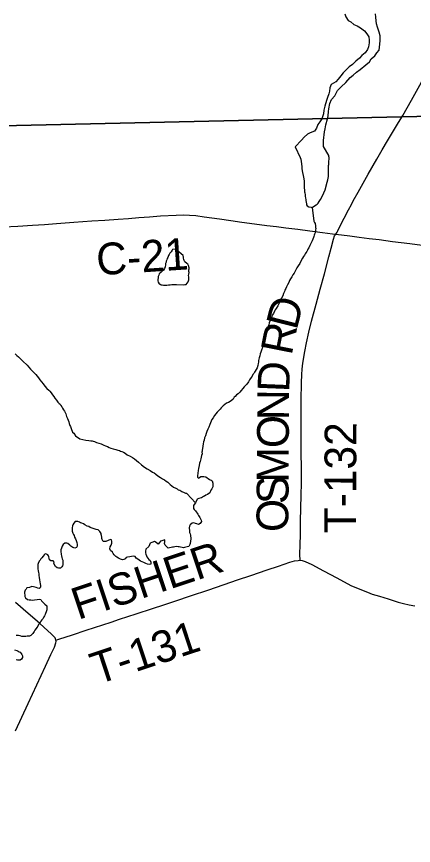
# Model space of a CAD drawing. Extents: x 103424 to 290657, y 38711 to 110967.
# Drawn here: x 153409 to 157176, y 64911 to 72783 of the extents above; entities that cross this region are included whole.
import ezdxf

# ---------------------------------------------------------------- set-up
doc = ezdxf.new("R2010")
doc.units = 0
for name, color, linetype in [('GM_X_Corporation', 7, 'Continuous'), ('GM_X_County_Road', 7, 'Continuous'), ('GM_X_County_Road_Text', 7, 'Continuous'), ('GM_X_Minor_Lake', 7, 'Continuous'), ('GM_X_Minor_River', 7, 'Continuous'), ('GM_X_Township_Road', 7, 'Continuous'), ('GM_X_Township_Road_Text', 7, 'Continuous')]:
    doc.layers.add(name, color=color, linetype=linetype)

msp = doc.modelspace()

# ---------------------------------------------------------------- linework, layer by layer
at = {"layer": 'GM_X_Corporation'}
for points in [[(148594.2, 97294.7), (158050.5, 97608.1), (158064.2, 97608.5), (162306.4, 97749.1), (162479.3, 97753.8), (165116.9, 97825.6), (173478.4, 98058.2), (173550.7, 94746.5), (173649.8, 90059.6), (173693.6, 87690.3), (173775.2, 84514.7), (174054.1, 73155.3), (174066.9, 72315.5), (174070.5, 72208.9), (173777.3, 72202), (169136.7, 72130.4), (166950.9, 72068.3), (161596.3, 71930.5), (161287.7, 71923.7), (157064.3, 71829.7), (151578, 71707.7), (149073.5, 71652)], [(149073.5, 71652), (151578, 71707.7), (157064.3, 71829.7), (161287.7, 71923.7), (161596.3, 71930.5), (166950.9, 72068.3), (169136.7, 72130.4), (173777.3, 72202), (174070.5, 72208.9), (174125.3, 69464.1), (174128.9, 69223), (174137.2, 68978.3), (174140.8, 68790.7), (174153.5, 68330.8), (174162.2, 67903.5), (174163.3, 67850.7), (174375.3, 58453.3)]]:
    msp.add_lwpolyline(points, dxfattribs=at)
at = {"layer": 'GM_X_County_Road'}
for points in [[(153285.8, 70784.8), (153422.5, 70792.7), (153559.2, 70800.6), (153674.3, 70809.2), (153789.5, 70817.8), (153954.1, 70829.9), (154038.1, 70836), (154122.2, 70842.2), (154247.8, 70850.5), (154373.5, 70858.9), (154471, 70866.5), (154568.5, 70874), (154672.3, 70881.8), (154776.1, 70889.6), (154925.6, 70898.2), (154989.7, 70899.3), (155111.7, 70894), (155189.7, 70882.6), (155335.4, 70860.8), (155441.7, 70845.8), (155548, 70830.8), (155666.6, 70815.6), (155785.2, 70800.3), (155875.8, 70788.4), (155966.4, 70776.4), (156079.1, 70762.6), (156191.7, 70748.8), (156314.9, 70732.3), (156408.7, 70720.9), (156439.3, 70716.8), (156573.5, 70699.1), (156661.5, 70687.9), (156755.7, 70676.4), (156849.9, 70664.9), (156978.6, 70648), (157142.3, 70626.5), (157306, 70605)], [(153399.6, 66000.6), (153459, 66129.5), (153518.5, 66258.3), (153559.5, 66347.1), (153600.6, 66435.9), (153641.6, 66524.2), (153682.6, 66612.6), (153735.9, 66725.5), (153768.3, 66794.8), (153783.1, 66834.6), (153784.3, 66848.1), (153782.4, 66860.9), (153780.2, 66872.7), (153774.5, 66883), (153738.3, 66920.7), (153672.3, 66980.2), (153626, 67020.8), (153519.3, 67113.1), (153398.5, 67219.1)]]:
    msp.add_lwpolyline(points, dxfattribs=at)
at = {"layer": 'GM_X_Minor_Lake'}
for points in [[(156526.8, 72808.9), (156534.9, 72780.7), (156557.3, 72746.5), (156583.5, 72734.5), (156609.8, 72708.5), (156642.1, 72694.5), (156674.4, 72676.5), (156710.8, 72646.5), (156735.1, 72618.3), (156753.3, 72592.2), (156757.5, 72559.9), (156757.6, 72533.7), (156749.7, 72497.3), (156741.7, 72469.1), (156717.7, 72438.7), (156687.5, 72414.3), (156663.4, 72387.9), (156631.3, 72359.5), (156599.2, 72327), (156567, 72306.7), (156510.8, 72249.9), (156488.8, 72221.5), (156460.7, 72189.1), (156438.6, 72162.7), (156396.4, 72138.3), (156384.4, 72105.9), (156378.5, 72075.6), (156374.5, 72049.4), (156360.6, 72015), (156350.6, 71986.7), (156334.7, 71932.1), (156324.8, 71893.7), (156322.9, 71859.4), (156306.9, 71812.9), (156286.9, 71784.5), (156268.9, 71758.2), (156256.9, 71721.8), (156236.9, 71695.5), (156196.6, 71679.1), (156170.5, 71666.9), (156140.4, 71638.5), (156114.3, 71610.1), (156054.5, 71545.1)], [(156323.8, 71549.1), (156323.9, 71605.2), (156325.8, 71633.4), (156329.7, 71659.7), (156331.6, 71687.9), (156339.6, 71716.2), (156345.5, 71754.6), (156359.3, 71813.2), (156367.3, 71839.5), (156369.2, 71881.8), (156373.1, 71908.1), (156383, 71958.6), (156398.9, 71995), (156429, 72031.5), (156455, 72082.1), (156491.2, 72114.6), (156533.3, 72157.2), (156575.5, 72203.8), (156603.6, 72226.2), (156635.7, 72256.6), (156669.9, 72281), (156724.1, 72325.7), (156760.3, 72352.1), (156776.3, 72382.5), (156810.5, 72410.9), (156830.5, 72439.3), (156852.6, 72465.6), (156858.4, 72520.1), (156862.3, 72554.4), (156860.1, 72598.8), (156849.9, 72635.1), (156835.6, 72681.4), (156827.4, 72715.7), (156823.3, 72741.9), (156819.1, 72776.2), (156817, 72810.5)], [(156054.5, 71545.1), (156102.2, 71444), (156108.6, 71428), (156111.1, 71405.8), (156115.6, 71383.7), (156118.2, 71357.5), (156118.6, 71339.4), (156121, 71319.2), (156132.5, 71256.9), (156136.8, 71242.8), (156139.3, 71218.7), (156139.7, 71202.5), (156140.1, 71182.4), (156140.4, 71168.2), (156140.7, 71152.1), (156141.1, 71137.9), (156143.5, 71117.8), (156145.7, 71107.8), (156148.1, 71089.6), (156148.4, 71077.5), (156150.8, 71059.4), (156155.1, 71045.4), (156155.4, 71035.3), (156157.7, 71021.2), (156162.1, 71005.1), (156162.3, 70995.1), (156166.5, 70985), (156182.9, 70975.3), (156205.2, 70971.8), (156215.4, 70970), (156237.2, 70986.6), (156253.2, 70995), (156263.2, 71001.3), (156271.1, 71011.5), (156282.9, 71025.9), (156294.6, 71044.4), (156310.1, 71075), (156327.6, 71109.7), (156339.2, 71136.2), (156357.8, 71209.3), (156363.4, 71231.6), (156367.1, 71247.8), (156368.8, 71264), (156370.4, 71282.3), (156370, 71302.4), (156369.6, 71320.6), (156369.3, 71332.7), (156368.9, 71352.9), (156370.6, 71367.1), (156372.4, 71379.2), (156374.1, 71393.4), (156373.8, 71409.5), (156375.4, 71427.7), (156375.1, 71443.9), (156374.9, 71454), (156374.6, 71464.1), (156323.8, 71549.1)], [(154890.1, 70570.6), (154886, 70565.5), (154876.3, 70547.1), (154864.4, 70534.8), (154856.5, 70524.5), (154852.7, 70514.3), (154845, 70496), (154839.2, 70483.8), (154835.4, 70473.6), (154829.6, 70461.3), (154827.8, 70449.2), (154824, 70439), (154822.3, 70424.8), (154818.6, 70406.6), (154812.9, 70390.3), (154805.1, 70376), (154791.3, 70363.6), (154777.3, 70353.2), (154763.4, 70340.8), (154759.7, 70328.6), (154753.9, 70314.3), (154752.1, 70302.2), (154750.5, 70286), (154750.7, 70273.9), (154753, 70261.8), (154761.4, 70245.8), (154771.7, 70240), (154781.8, 70236.2), (154792, 70234.4), (154804.2, 70230.6), (154820.4, 70231), (154834.4, 70233.3), (154850.6, 70235.7), (154866.7, 70236), (154882.8, 70238.4), (154897, 70238.7), (154913.2, 70237), (154927.3, 70237.3), (154992, 70236.7), (155006.1, 70239), (155018.2, 70239.3), (155028.1, 70249.6), (155037.9, 70263.9), (155043.6, 70282.2), (155043.3, 70296.4), (155043, 70310.5), (155042.7, 70324.6), (155044.5, 70336.8), (155046.2, 70350.9), (155045.9, 70363.1), (155045.6, 70377.2), (155047.4, 70387.3), (155047.2, 70397.4), (155042.7, 70417.5), (155034.4, 70431.5), (155024.1, 70439.3), (155007.6, 70455.1), (154999.3, 70465), (154997, 70477.1), (154994.8, 70487.1), (154992.5, 70499.2), (154992.2, 70513.3), (154919.3, 70573)], [(154919.3, 70573), (154890.1, 70570.6)]]:
    msp.add_lwpolyline(points, dxfattribs=at)
at = {"layer": 'GM_X_Minor_River'}
for points in [[(156215.4, 70970), (156230.3, 70839), (156236.6, 70827.1), (156242.9, 70817.1), (156247.4, 70795), (156247.7, 70780.9), (156249.9, 70770.8), (156248.2, 70758.7), (156246.5, 70742.5), (156242.8, 70728.3), (156239, 70716.1), (156235.1, 70705.9), (156231.3, 70695.7), (156227.5, 70683.5), (156221.8, 70669.2), (156214, 70652.9), (156208.2, 70640.7), (156192.8, 70608.1), (156183.1, 70587.6), (156175.3, 70575.4), (156171.4, 70565.2), (156163.7, 70550.9), (156155.8, 70540.6), (156149.9, 70530.4), (156142.2, 70516.1), (156134.3, 70505.8), (156124.5, 70489.5), (156110.9, 70464.9), (156099.4, 70438.4), (156083.7, 70415.9), (156070, 70395.4), (156058.3, 70372.9), (156044.7, 70346.4), (156030.9, 70329.9), (156021.2, 70311.5), (156009.5, 70291.1), (156001.7, 70276.8), (155994, 70258.5), (155982.4, 70234), (155972.7, 70215.6), (155964.9, 70201.3), (155957.2, 70185), (155951.4, 70172.7), (155941.7, 70152.3), (155938.1, 70132.1), (155924.5, 70107.5), (155912.9, 70085.1), (155903.3, 70060.6), (155889.6, 70036.1), (155872, 70009.5), (155864.2, 69997.2), (155858.4, 69984.9), (155846.7, 69964.5), (155837, 69946.1), (155831.2, 69933.9), (155825.4, 69919.6), (155819.7, 69905.4), (155811.9, 69889), (155808.2, 69872.8), (155802.5, 69856.5), (155796.8, 69840.3), (155791.1, 69824), (155787.3, 69809.8), (155781.7, 69789.5), (155776.2, 69765.1), (155759.1, 69710.2), (155757.4, 69696), (155753.7, 69679.8), (155748, 69663.5), (155742.5, 69639.2), (155734.9, 69614.8), (155727.2, 69596.5), (155721.5, 69580.2), (155717.8, 69561.9), (155712.2, 69541.6), (155708.4, 69529.4), (155706.7, 69517.3), (155705, 69501.1), (155703.3, 69486.9), (155699.6, 69468.6), (155692, 69448.3), (155684.2, 69432), (155674.5, 69415.6), (155666.6, 69405.3), (155660.8, 69393.1), (155652.9, 69382.8), (155645.2, 69366.5), (155635.3, 69354.2), (155621.6, 69333.7), (155609.9, 69315.3), (155594.2, 69292.7), (155570.5, 69266), (155556.7, 69249.5), (155540.9, 69233), (155527.1, 69216.6), (155511.3, 69200.1), (155497.4, 69189.7), (155485.5, 69175.3)], [(153397.2, 69580.2), (153411.7, 69564.3), (153426.1, 69552.5), (153438.5, 69540.7), (153453, 69524.8), (153467.4, 69509), (153510.7, 69471.6), (153527.2, 69453.8), (153541.8, 69433.9), (153560.4, 69414.1), (153576.9, 69398.3), (153593.4, 69382.5), (153605.8, 69368.7), (153618.3, 69350.8), (153630.9, 69332.9), (153647.4, 69315.1), (153662, 69295.2)], [(153662, 69295.2), (153678.6, 69273.3), (153697.3, 69249.5), (153715.8, 69235.8), (153726.1, 69223.9), (153736.6, 69208), (153751.1, 69190.1), (153763.6, 69174.2), (153774, 69160.3), (153788.6, 69140.4), (153801.1, 69120.5), (153813.5, 69108.7), (153823.8, 69100.8), (153830.1, 69088.8), (153838.4, 69076.9), (153846.8, 69065), (153855.2, 69049), (153863.6, 69035), (153869.9, 69023.1), (153876.2, 69009.1), (153882.8, 68985), (153891.3, 68965), (153897.7, 68949), (153904.1, 68933), (153908.5, 68918.9), (153915, 68898.9), (153921.2, 68888.9), (153927.7, 68870.9), (153940.6, 68834.8), (153952.9, 68827), (153969.6, 68801.1), (154008.6, 68771.7), (154065.4, 68760.8), (154095.9, 68755.4), (154114.1, 68753.8), (154126.3, 68752), (154136.4, 68750.2), (154150.6, 68746.5), (154169, 68738.8), (154189.4, 68731.2), (154213.8, 68723.6), (154236.2, 68714), (154254.6, 68706.3), (154272.9, 68698.7), (154289.2, 68691), (154303.5, 68685.2), (154325.9, 68677.6), (154350.3, 68672.1), (154370.6, 68666.5), (154386.9, 68662.8), (154397.1, 68657), (154409.3, 68651.2), (154423.6, 68645.4), (154440, 68635.7), (154458.5, 68621.9), (154487.1, 68608.4), (154509.6, 68594.8), (154528.1, 68581.1), (154546.5, 68567.3), (154567.1, 68549.6), (154593.9, 68525.9), (154622.7, 68504.3), (154649.3, 68486.8), (154675.9, 68471.2), (154698.4, 68457.5), (154714.8, 68449.8), (154731.2, 68436), (154751.8, 68420.3), (154774.3, 68406.7), (154794.8, 68393), (154813.2, 68383.3), (154829.6, 68371.5), (154844, 68361.8), (154856.4, 68349.9), (154868.7, 68340.1), (154899.6, 68314.5), (154920, 68304.9), (154932.3, 68297.1), (154944.6, 68289.2), (154958.8, 68283.5), (154969.1, 68277.7), (154979.3, 68271.8), (154999.7, 68262.2), (155012, 68256.4), (155022.1, 68256.6), (155024.1, 68254.6), (155108.9, 68163.6)], [(155485.5, 69175.3), (155473.6, 69168.9), (155465.9, 69148.6), (155446, 69134), (155422.1, 69117.4), (155402, 69110.9), (155370.2, 69085.9), (155360.3, 69077.6), (155350.4, 69067.3), (155342.6, 69055.1), (155326.8, 69038.6), (155312.9, 69026.1), (155301.1, 69009.7), (155289.3, 68993.3), (155275.7, 68970.8), (155261.8, 68956.4), (155258.1, 68940.2), (155244.6, 68909.6), (155233.1, 68883.1), (155223.4, 68864.7), (155215.7, 68842.3), (155208, 68824), (155202.5, 68801.6), (155194.8, 68781.3), (155189.2, 68761), (155183.5, 68742.7), (155179.9, 68724.4), (155176.3, 68702.1), (155172.7, 68679.8), (155171, 68665.7), (155171.2, 68655.6), (155169.4, 68645.5), (155169.7, 68631.3), (155166, 68615.1), (155162.3, 68598.9), (155158.6, 68582.6), (155154.8, 68570.4), (155151.1, 68558.2), (155145.3, 68542), (155141.8, 68519.7), (155136.3, 68491.3), (155132.6, 68473), (155127.7, 68422.4), (155125.9, 68408.3), (155136.2, 68400.4), (155158.1, 68415), (155168.2, 68415.2), (155186.5, 68413.6), (155204.7, 68412), (155217, 68402.2), (155229.3, 68396.4), (155241.6, 68386.6), (155255.9, 68378.8), (155266.1, 68375), (155272.6, 68352.9), (155273, 68336.8), (155271.4, 68316.5), (155261.7, 68296.1), (155253.9, 68285.9), (155242.3, 68259.4), (155222.4, 68244.8), (155204.4, 68236.3), (155192.4, 68228), (155182.4, 68225.8), (155164.5, 68213.3), (155140.3, 68206.7), (155122.3, 68198.2), (155108.9, 68163.6), (155095.1, 68149.2), (155089.2, 68138.9), (155089.5, 68124.8), (155089.8, 68110.7), (155096.1, 68100.7), (155106.5, 68088.8), (155112.8, 68078.9), (155123.1, 68067), (155131.4, 68057.1), (155137.7, 68045.1), (155150.3, 68025.2), (155154.6, 68013.2), (155160.9, 67999.1), (155163.2, 67987.1), (155151.5, 67968.7), (155135.5, 67960.2), (155119.2, 67965.9), (155109, 67969.8), (155092.8, 67973.4), (155076.6, 67973.1), (155056.8, 67954.5), (155051, 67944.3), (155047.3, 67926), (155049.9, 67897.8), (155052.2, 67883.7), (155056.6, 67869.7), (155060.9, 67857.7), (155063.6, 67823.4), (155060.1, 67799.1), (155058.5, 67778.9), (155054.7, 67768.7), (155043, 67750.3), (155028.9, 67745.9)], [(155028.9, 67745.9), (155004.8, 67739.3), (154994.7, 67737.1), (154980.5, 67740.8), (154966.3, 67742.5), (154954.1, 67746.3), (154941.9, 67748.1), (154927.7, 67749.8), (154911.6, 67747.4), (154899.6, 67745.1), (154889.5, 67742.9), (154875.4, 67740.6), (154861.3, 67736.2), (154847.2, 67733.9), (154820.4, 67761.6), (154813.9, 67779.6), (154815.6, 67795.8), (154815.3, 67811.9), (154787.2, 67803.3), (154777.1, 67801), (154767.3, 67788.7), (154753.5, 67772.2), (154732.9, 67787.9), (154718.6, 67797.7), (154694.5, 67787.1), (154676.4, 67782.7), (154665, 67750.1), (154637.2, 67725.3), (154633.6, 67705), (154633.9, 67690.9), (154636.3, 67676.8), (154642.7, 67660.8), (154646.9, 67650.8), (154655.2, 67638.9), (154663.6, 67626.9), (154675.9, 67617.1), (154684.3, 67601.1), (154682.7, 67582.9), (154668.7, 67578.6), (154652.4, 67582.3), (154636.1, 67588), (154617.7, 67597.7), (154601.4, 67603.4), (154585.1, 67611.1), (154572.8, 67618.9), (154560.5, 67628.7), (154546.1, 67640.5), (154533.6, 67654.4), (154515.4, 67658), (154485.2, 67653.3), (154461, 67648.8), (154451, 67646.5), (154441.1, 67634.2), (154427.1, 67627.9), (154415.1, 67623.5), (154394.7, 67631.2), (154376.3, 67638.9), (154362, 67648.7), (154351.7, 67656.5), (154337.2, 67672.3), (154324.8, 67684.2), (154320.5, 67696.2), (154300, 67711.9), (154293.6, 67727.9), (154297.2, 67746.2), (154307, 67762.6), (154314.7, 67782.9), (154314.3, 67801.1), (154312, 67813.1), (154299.8, 67816.9), (154279.8, 67806.4), (154257.7, 67797.8), (154241.6, 67797.5), (154231.5, 67797.2), (154223, 67815.2), (154218.7, 67827.3), (154218.5, 67837.3), (154216.1, 67853.5), (154213.9, 67863.5), (154211.7, 67873.5), (154199.1, 67893.5), (154184.7, 67907.3), (154166.4, 67910.9), (154109.4, 67931.9), (154095.1, 67939.7), (154080.8, 67943.4), (154058.3, 67957), (154046, 67964.8), (154029.7, 67970.5), (154015.5, 67976.3), (154005.3, 67980.1), (153991, 67985.9), (153978.8, 67987.6), (153964.7, 67987.3), (153952.9, 67970.9), (153943.1, 67956.6), (153939.3, 67946.4), (153935.7, 67926.1), (153935.9, 67914), (153938.3, 67895.9), (153942.8, 67875.8)], [(153942.8, 67875.8), (153949.1, 67863.8), (153955.4, 67853.8), (153959.7, 67839.8), (153968.2, 67821.8), (153974.6, 67807.8), (153976.8, 67797.8), (153981.1, 67787.8), (153985.5, 67767.7), (153983.8, 67753.5), (153978, 67741.3), (153962, 67734.9), (153943.7, 67740.5), (153925.2, 67754.2), (153914.9, 67764.1), (153896.4, 67777.9), (153886.2, 67781.7), (153876.1, 67781.4), (153866, 67783.2), (153852.1, 67768.8), (153842.3, 67754.5), (153836.7, 67734.2), (153831, 67717.9), (153829.4, 67697.7), (153831.7, 67683.6), (153831.9, 67673.5), (153836.2, 67661.5), (153838.6, 67645.4), (153842.9, 67631.3), (153847.2, 67619.3), (153849.5, 67605.2), (153849.9, 67587.1), (153848.1, 67576.9), (153844.3, 67566.7), (153838.5, 67556.5), (153826.6, 67544.1), (153806.3, 67545.7), (153796.2, 67547.5), (153777.7, 67561.3), (153763, 67587.2), (153764.7, 67601.4), (153756.4, 67613.3), (153734.1, 67614.8), (153721.8, 67624.6), (153717.4, 67640.7), (153715.2, 67650.7), (153712.9, 67660.8), (153704.7, 67670.7), (153694.4, 67678.6), (153682.2, 67680.3), (153670.3, 67670), (153662.4, 67659.7), (153648.6, 67643.3), (153640.8, 67633), (153633, 67620.7), (153623.1, 67610.4), (153615.4, 67590), (153611.6, 67577.8), (153610, 67559.6), (153610.5, 67537.4), (153614.9, 67519.3), (153617.3, 67503.2), (153619.5, 67491.2), (153621.9, 67475.1), (153624.4, 67455), (153626.8, 67434.8), (153631.3, 67414.7), (153633.7, 67396.6), (153636, 67380.5), (153636.3, 67368.4), (153634.6, 67356.2), (153624.5, 67352), (153612.4, 67353.7), (153596, 67361.5), (153583.8, 67365.2), (153569.6, 67366.9), (153555.4, 67370.7), (153533.4, 67362.1), (153507.2, 67357.5), (153501.4, 67343.2), (153491.5, 67334.9), (153485.8, 67316.7), (153486, 67306.6), (153486.4, 67288.4), (153488.8, 67274.3), (153495.1, 67262.3), (153513.6, 67246.6), (153527.8, 67242.9), (153546, 67243.3), (153562.2, 67241.6), (153580.4, 67244), (153604.5, 67246.5), (153624.7, 67249), (153638.9, 67245.3), (153647.2, 67235.4), (153661.8, 67217.5), (153678.2, 67203.7), (153696.8, 67186), (153697.3, 67159.7), (153695.6, 67147.6), (153689.9, 67129.3)], [(153689.9, 67129.3), (153684.1, 67115), (153680.4, 67102.8), (153674.5, 67092.6), (153668.7, 67082.4), (153660.9, 67066.1), (153649.1, 67053.7), (153639.2, 67041.3), (153631.5, 67023), (153617.7, 67010.6), (153609.9, 66994.3), (153600.1, 66981.9), (153594.3, 66969.7), (153582.5, 66955.3), (153576.7, 66943.1), (153568.8, 66932.8), (153562.9, 66922.6), (153545.1, 66904), (153531.1, 66897.7), (153510.9, 66897.2), (153496.8, 66894.9), (153478.7, 66894.5), (153460.4, 66896.1), (153442.1, 66901.8), (153427.9, 66903.5), (153417.8, 66905.3), (153405.7, 66905)], [(153388.4, 66767.3), (153410.8, 66761.8), (153423, 66756), (153433.2, 66750.2), (153443.4, 66746.3), (153451.8, 66734.4), (153460, 66724.5), (153466.4, 66710.5), (153466.7, 66696.4), (153456.9, 66680), (153445, 66671.7), (153432.9, 66669.4), (153418.7, 66671.1), (153406.5, 66674.9)]]:
    msp.add_lwpolyline(points, dxfattribs=at)
at = {"layer": 'GM_X_Township_Road'}
for points in [[(157076.1, 71844.5), (157156.7, 71988.6), (157237.3, 72132.6), (157318, 72276.6), (157398.6, 72420.7), (157450.7, 72513.8), (157502.9, 72606.9)], [(156587.2, 70998.9), (156605, 71031.7), (156650.8, 71116), (156698.7, 71201.1), (156746.6, 71286.2), (156829.4, 71429), (156879.9, 71516), (156930.4, 71603), (156978, 71681.4), (157025.7, 71759.7), (157066.2, 71826.8), (157076.1, 71844.5)], [(156439.3, 70716.8), (156453.3, 70735.3), (156459.6, 70749.7), (156477.5, 70789.9), (156518.4, 70868.7), (156559.2, 70947.4), (156587.2, 70998.9)], [(156100.1, 67618.8), (156099.5, 67674.7), (156101.4, 67768.1), (156103.2, 67861.4), (156105.9, 67988.7), (156108.6, 68115.9), (156111.1, 68235.6), (156113.5, 68355.2), (156112.8, 68497.8), (156112.1, 68640.3), (156111.2, 68752.3), (156110.3, 68864.2), (156109.9, 69002.6), (156109.5, 69141), (156112.6, 69304), (156116.7, 69385), (156121.2, 69435.8), (156127.5, 69489.9), (156146, 69600.8), (156160.9, 69683.4), (156184.6, 69787.2), (156208.3, 69890.9), (156251.7, 70050.2), (156291.3, 70195.5), (156330.9, 70340.8), (156373.6, 70500.3), (156396.3, 70584.9), (156419, 70669.5), (156428.7, 70699.1), (156439.3, 70716.8)], [(153782.4, 66860.9), (153811.4, 66870.6), (153940.8, 66912.3), (154070.2, 66954), (154226.8, 67006), (154306.6, 67032.4), (154386.4, 67058.9), (154543.3, 67110.2), (154700.2, 67161.4), (154806.3, 67196.1), (154912.3, 67230.7), (155068.7, 67283.6), (155225, 67336.6), (155381.4, 67389.5), (155506.5, 67431.8), (155631.6, 67474.2), (155788.1, 67526.8), (155896.3, 67563.2), (156004.5, 67599.6), (156046.5, 67613.7), (156082, 67618.5), (156100.1, 67618.8), (156121.8, 67617.4), (156148.3, 67607.4), (156211.5, 67578.7), (156322.9, 67520.3), (156448.6, 67450.8), (156583.9, 67380.8), (156666.7, 67343.2), (156739.3, 67316.1), (156785.7, 67298.1), (156820.2, 67287.4), (156854.6, 67276.7), (156935.7, 67251.4), (157030.1, 67222), (157083.1, 67207.9), (157137.2, 67194.6), (157189.2, 67187.2)]]:
    msp.add_lwpolyline(points, dxfattribs=at)

# ---------------------------------------------------------------- texts
at = {"layer": 'GM_X_County_Road_Text'}
msp.add_text('C-21', height=301.87, rotation=3.76908, dxfattribs=at).set_placement((154175.8, 70325.3))
at = {"layer": 'GM_X_Township_Road_Text'}
for s, height, rotation, p in [('D', 301.9, 75.77467, (156067.4, 69796.5)), ('R', 301.9, 78.7934, (156020.1, 69557.4)), ('D', 301.9, 87.70079, (155996.7, 69212.4)), ('N', 301.9, 89.60656, (155994.9, 68949.4)), ('O', 301.9, 89.64299, (155993.3, 68683.8)), ('T-132', 301.87, 89.71774, (156631.1, 67874.6)), ('M', 301.9, 89.64835, (155991.2, 68356.2)), ('S', 301.9, 89.64362, (155990, 68152.5)), ('O', 301.9, 89.64663, (155988.3, 67886.9)), ('FISHER', 301.87, 18.43471, (153993.1, 67051.9)), ('T-131', 301.87, 18.25686, (154173.3, 66436))]:
    msp.add_text(s, height=height, rotation=rotation, dxfattribs=at).set_placement(p)

doc.saveas('drawing.dxf')
